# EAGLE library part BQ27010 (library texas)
Li-Ion AND Li-Pol BATTERY GAS GAUGE IC FOR PORTABLE APPLICATIONS HDQ Communication (bqJUNIOR) Source: www.ti.com .. bq27010.pdf
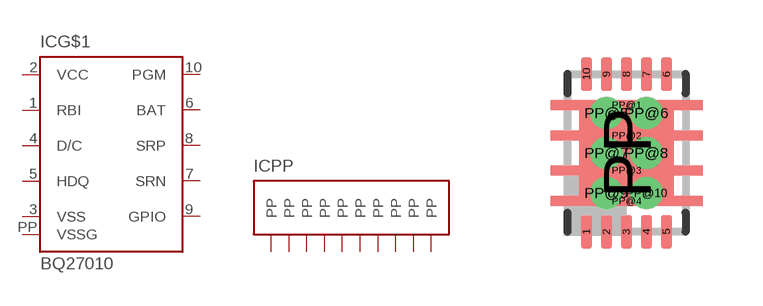
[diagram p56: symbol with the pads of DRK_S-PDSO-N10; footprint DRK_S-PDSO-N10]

Designator prefix IC; gates G$1=BQ27010 PP=PWR-PP10

## BQ27010 (MPN: BQ27010DRKR; OC_FARNELL: unknown; OC_NEWARK: 02M9376)  [DRK_S-PDSO-N10]
1  G$1:RBI  in
2  G$1:VCC  pwr
3  G$1:VSS  pwr
4  G$1:D/C  in
5  G$1:HDQ
6  G$1:BAT  in
7  G$1:SRN  in
8  G$1:SRP  in
9  G$1:GPIO
10  G$1:PGM  in
PP  G$1:VSSG  pwr
PP@1  PP:PP  pwr
PP@2  PP:PP  pwr
PP@3  PP:PP  pwr
PP@4  PP:PP  pwr
PP@5  PP:PP  pwr
PP@6  PP:PP  pwr
PP@7  PP:PP  pwr
PP@8  PP:PP  pwr
PP@9  PP:PP  pwr
PP@10  PP:PP  pwr

## Footprint DRK_S-PDSO-N10 (pad centres in mm)
DRK (S-PDSO-N10) Source: www.ti.com .. bq27010.pdf
smd 0.28 x 0.85: 1 -1,-1.975; 2 -0.5,-1.975; 3 0,-1.975; 4 0.5,-1.975; 5 1,-1.975; 6 1,1.975; 7 0.5,1.975; 8 0,1.975; 9 -0.5,1.975; 10 -1,1.975
smd 2.35 x 2.65: PP 0,0
smd 3.8 x 0.25: PP@1 0,1.2; PP@2 0,0.435; PP@3 0,-0.435; PP@4 0,-1.2
drill 0.3 pad 0.5 round: PP@5 -0.5,1; PP@6 0.5,1; PP@7 -0.5,0; PP@8 0.5,0; PP@9 -0.5,-1; PP@10 0.5,-1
